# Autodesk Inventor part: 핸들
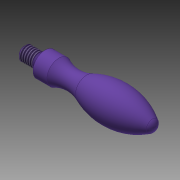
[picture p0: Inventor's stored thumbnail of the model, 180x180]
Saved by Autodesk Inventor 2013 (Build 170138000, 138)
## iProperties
Created: 2019-10
Part Number: 핸들
Material: 스테인리스강
Document SubType Name: Modeling
Designer: mduedu
Density: 1 g/cm^3
Author: mduedu
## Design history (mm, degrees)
sketch "스케치1"
  geometry: L1 (0, 0)-(0, 2); L2 (0, 2)-(4.35, 2); L3 (6, 1.45)-(6, 3.5); L4 (6, 3.5)-(10, 3.5); L5 (0, 0)-(38, 0); L6 (4.9, 1.45)-(6, 1.45); L7 (4.9, 1.45)-(4.35, 2); A1 r 9.5 centre (14.243, 12) between (10, 3.5) and (18.07, 3.305); A2 r 20 centre (26.128, -15) between (37.049, 1.754) and (18.07, 3.305); A3 r 2.094 centre (35.906, 0) between (38, 0) and (37.049, 1.754)
  constraints: 14 end point, 6 point on circle, 3 centre point, 3 parallel, 2 tangent, 1 perpendicular, 1 point on line, 1 vertical
  dimensions: "d1" = 4 diameter of L2 L5; "d2" = 7 diameter of L4 L5; "d4" = 4 distance of L3.end L4.end; "d5" = 5 dimension on A1 L5; "d6" = 9.5 radius of A1; "d7" = 10 dimension on A2 L5; "d8" = 20 radius of A2; "d15" = 6 distance between parallel lines of L1 L3; "d16" = 38 distance from line of L5.end L1; "d17" = 2.9 diameter of L6 L5 (computed from d1); "d19" = 1.1 distance of L6.start L3.start; "d20" = 135 deg angle of L7 L6
revolve "회전1" sketch "스케치1" stored, may be unused: angle "d9" = 90 deg
feature "스레드1" dims "d10" = 5, "d11" = 0
chamfer "모따기1" distance "d12" = 0.5; stored, may be unused: second distance "d13" = 2, angle "d14" = 45 deg
fillet "모깎기1" dims "d21" = 0.4
node "솔리드1"
